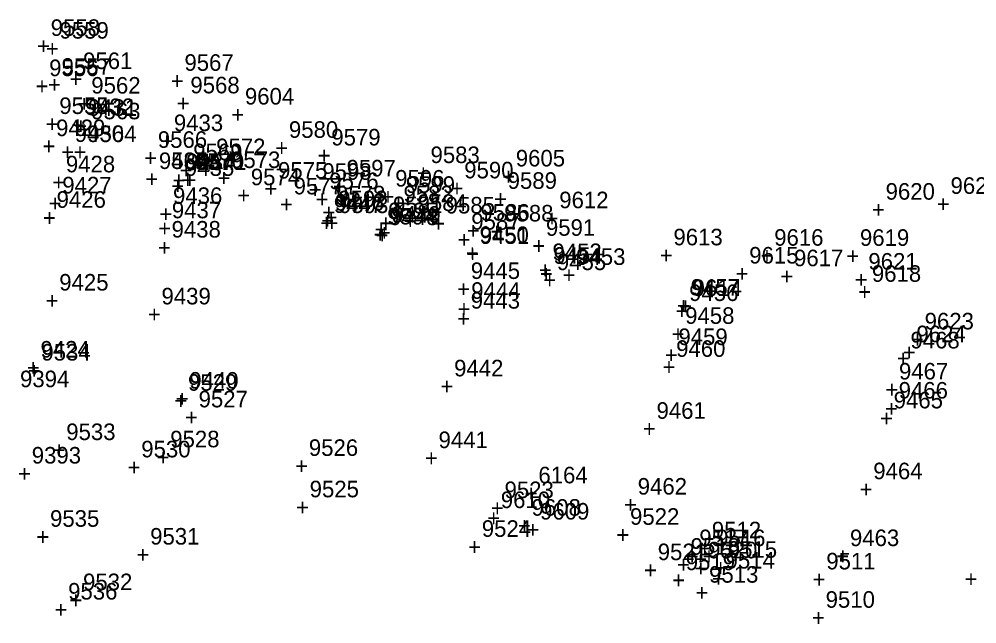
# Model space of a CAD drawing. Extents: x 1136220 to 1137808, y 528804 to 531215.
# Drawn here: x 1136494.7 to 1136639.3, y 529219.5 to 529310.9 of the extents above; entities that cross this region are included whole.
import ezdxf

# ---------------------------------------------------------------- set-up
doc = ezdxf.new("R2010")
doc.units = 0
for name, color, linetype in [('S_Buildings', 7, 'Continuous'), ('S_Buildings_Attachments', 7, 'Continuous'), ('S_Buildings_Steps_Brick', 7, 'Continuous'), ('S_Drainage_CB', 7, 'Continuous'), ('S_Fencing_ChainLink', 7, 'Continuous'), ('S_Fencing_Gate', 7, 'Continuous'), ('S_Fencing_Picket', 7, 'Continuous'), ('S_Ground_Elevation', 7, 'Continuous'), ('S_Ground_LevelString', 7, 'Continuous'), ('S_Property_Light', 7, 'Continuous'), ('S_RetWall_Top', 7, 'Continuous'), ('S_Roadway_Centerline', 7, 'Continuous'), ('S_Roadway_Drive_Gravel', 7, 'Continuous'), ('S_Roadway_Drive_Paved', 7, 'Continuous'), ('S_Roadway_Edge_Pavement', 7, 'Continuous'), ('S_Roadway_Sidewalks', 7, 'Continuous'), ('S_Traffic_Sign_SinglePost', 7, 'Continuous'), ('S_Trees_Bush', 7, 'Continuous'), ('S_Trees_Decid_Pay', 7, 'Continuous'), ('S_Trees_HedgeLine', 7, 'Continuous'), ('S_Utilities_Pole_Power', 7, 'Continuous'), ('S_Utilities_UG_Gas_Line', 7, 'Continuous')]:
    doc.layers.add(name, color=color, linetype=linetype)

msp = doc.modelspace()

# ---------------------------------------------------------------- texts
at = {"layer": 'S_Buildings'}
for s, p in [('9604', (1136528.8, 529297.96)), ('+', (1136526.74, 529295.21)), ('9605', (1136569.68, 529288.61)), ('+', (1136567.62, 529285.86))]:
    msp.add_text(s, height=2.5, dxfattribs=at).set_placement(p)
at = {"layer": 'S_Buildings_Attachments'}
for s, p in [('9598', (1136540.49, 529286.6)), ('+', (1136538.43, 529283.85)), ('9599', (1136553.08, 529284.62)), ('+', (1136551.02, 529281.87))]:
    msp.add_text(s, height=2.5, dxfattribs=at).set_placement(p)
at = {"layer": 'S_Buildings_Steps_Brick'}
for s, p in [('9597', (1136544.14, 529287.1)), ('9596', (1136551.48, 529285.57)), ('+', (1136542.08, 529284.35)), ('9592', (1136542.89, 529282.45)), ('+', (1136549.42, 529282.82)), ('9593', (1136543.01, 529281.57)), ('9595', (1136550.44, 529280.64)), ('+', (1136540.83, 529279.7)), ('9594', (1136550.28, 529279.85)), ('+', (1136540.95, 529278.82)), ('+', (1136548.22, 529277.1)), ('+', (1136548.38, 529277.89))]:
    msp.add_text(s, height=2.5, dxfattribs=at).set_placement(p)
at = {"layer": 'S_Drainage_CB'}
for s, p in [('9520', (1136598.7, 529229.43)), ('+', (1136596.64, 529226.68))]:
    msp.add_text(s, height=2.5, dxfattribs=at).set_placement(p)
at = {"layer": 'S_Fencing_ChainLink'}
for s, p in [('9535', (1136499.39, 529234.2)), ('+', (1136497.33, 529231.45)), ('9536', (1136502.12, 529223.21)), ('+', (1136500.06, 529220.46))]:
    msp.add_text(s, height=2.5, dxfattribs=at).set_placement(p)
at = {"layer": 'S_Fencing_Gate'}
for s, p in [('9433', (1136518.08, 529293.95)), ('+', (1136516.02, 529291.2)), ('9453', (1136578.79, 529273.74)), ('+', (1136576.73, 529270.99))]:
    msp.add_text(s, height=2.5, dxfattribs=at).set_placement(p)
at = {"layer": 'S_Fencing_Picket'}
for s, p in [('9432', (1136504.65, 529296.37)), ('9429', (1136500.3, 529293.19)), ('+', (1136502.59, 529293.62)), ('+', (1136498.24, 529290.44)), ('9434', (1136519.93, 529288.05)), ('+', (1136517.87, 529285.3)), ('9620', (1136625.49, 529283.59)), ('9446', (1136542.37, 529281.93)), ('+', (1136623.43, 529280.84)), ('9449', (1136550.92, 529280.12)), ('+', (1136540.31, 529279.18)), ('+', (1136548.86, 529277.37)), ('9450', (1136564.21, 529277.04)), ('9616', (1136608.68, 529276.64)), ('9619', (1136621.62, 529276.62)), ('+', (1136562.15, 529274.29)), ('9452', (1136575.21, 529274.47)), ('+', (1136606.62, 529273.89)), ('+', (1136619.55, 529273.87)), ('+', (1136573.15, 529271.72)), ('9457', (1136596.08, 529269.1)), ('9614', (1136596.37, 529269.03)), ('+', (1136594.02, 529266.35)), ('+', (1136594.31, 529266.28))]:
    msp.add_text(s, height=2.5, dxfattribs=at).set_placement(p)
at = {"layer": 'S_Ground_Elevation'}
for s, p in [('9558', (1136499.49, 529308.32)), ('+', (1136497.43, 529305.57)), ('9556', (1136499.26, 529302.25)), ('9568', (1136520.57, 529299.65)), ('+', (1136497.2, 529299.5)), ('+', (1136518.51, 529296.9)), ('9431', (1136505.11, 529296.25)), ('+', (1136503.05, 529293.5)), ('9430', (1136503.12, 529292.31)), ('9580', (1136535.44, 529292.93)), ('9579', (1136541.84, 529291.78)), ('+', (1136501.06, 529289.56)), ('9569', (1136521, 529289.55)), ('+', (1136533.37, 529290.18)), ('9583', (1136556.81, 529289.12)), ('9573', (1136526.71, 529288.37)), ('+', (1136539.78, 529289.03)), ('+', (1136518.94, 529286.8)), ('9590', (1136561.9, 529286.81)), ('+', (1136524.65, 529285.62)), ('+', (1136554.75, 529286.37)), ('9589', (1136568.45, 529285.23)), ('+', (1136559.83, 529284.06)), ('9584', (1136554.85, 529281.89)), ('+', (1136566.39, 529282.48)), ('9588', (1136567.93, 529280.3)), ('+', (1136552.79, 529279.14)), ('+', (1136565.86, 529277.55)), ('9613', (1136593.47, 529276.7)), ('+', (1136591.41, 529273.95)), ('9615', (1136604.91, 529273.95)), ('9617', (1136611.67, 529273.54)), ('+', (1136602.85, 529271.2)), ('+', (1136609.61, 529270.79)), ('9618', (1136623.42, 529271.19)), ('+', (1136621.36, 529268.44)), ('9394', (1136494.86, 529255.28)), ('9527', (1136521.81, 529252.23)), ('+', (1136519.75, 529249.48)), ('9528', (1136517.53, 529246.2)), ('9526', (1136538.45, 529244.9)), ('9393', (1136496.63, 529243.75)), ('+', (1136515.47, 529243.45)), ('+', (1136536.38, 529242.15)), ('+', (1136494.56, 529241)), ('9525', (1136538.57, 529238.65)), ('9523', (1136567.98, 529238.53)), ('+', (1136536.51, 529235.9)), ('+', (1136565.92, 529235.78)), ('9522', (1136586.92, 529234.5)), ('9524', (1136564.55, 529232.68)), ('+', (1136584.86, 529231.75)), ('9517', (1136597.38, 529231.27)), ('9512', (1136599.27, 529232.46)), ('9516', (1136599.92, 529231.27)), ('9518', (1136596.06, 529229.98)), ('+', (1136562.49, 529229.93)), ('9521', (1136591.1, 529229.16)), ('+', (1136597.21, 529229.71)), ('9515', (1136601.68, 529229.52)), ('+', (1136595.32, 529228.52)), ('9519', (1136595.33, 529227.65)), ('+', (1136597.86, 529228.52)), ('9514', (1136601.34, 529227.89)), ('9511', (1136616.54, 529227.76)), ('+', (1136589.04, 529226.41)), ('+', (1136594, 529227.23)), ('9513', (1136598.85, 529225.76)), ('+', (1136599.62, 529226.77)), ('+', (1136593.27, 529224.9)), ('+', (1136599.28, 529225.14)), ('+', (1136614.48, 529225.01)), ('+', (1136596.79, 529223.01)), ('9510', (1136616.44, 529221.97)), ('+', (1136614.38, 529219.22))]:
    msp.add_text(s, height=2.5, dxfattribs=at).set_placement(p)
at = {"layer": 'S_Ground_LevelString'}
for s, p in [('9428', (1136501.78, 529287.72)), ('+', (1136499.72, 529284.97)), ('9427', (1136501.24, 529284.54)), ('9436', (1136517.95, 529282.95)), ('+', (1136499.18, 529281.79)), ('9437', (1136517.77, 529280.78)), ('+', (1136515.89, 529280.2)), ('+', (1136515.71, 529278.03)), ('9445', (1136562.89, 529271.62)), ('+', (1136560.83, 529268.87)), ('9444', (1136562.95, 529268.62)), ('+', (1136560.89, 529265.87)), ('9458', (1136595.24, 529264.84)), ('+', (1136593.18, 529262.09)), ('9459', (1136594.22, 529261.64)), ('+', (1136592.16, 529258.89)), ('9467', (1136627.51, 529256.44)), ('+', (1136625.45, 529253.69)), ('9466', (1136627.46, 529253.56)), ('+', (1136625.39, 529250.81))]:
    msp.add_text(s, height=2.5, dxfattribs=at).set_placement(p)
at = {"layer": 'S_Property_Light'}
for s, p in [('9557', (1136501.13, 529302.46)), ('+', (1136499.07, 529299.71))]:
    msp.add_text(s, height=2.5, dxfattribs=at).set_placement(p)
at = {"layer": 'S_RetWall_Top'}
for s, p in [('9570', (1136521.25, 529288.09)), ('9571', (1136521.58, 529288.09)), ('+', (1136519.19, 529285.34)), ('+', (1136519.52, 529285.34)), ('9574', (1136529.69, 529285.77)), ('9577', (1136536.15, 529284.39)), ('+', (1136527.63, 529283.02)), ('9578', (1136542.55, 529283.18)), ('+', (1136534.09, 529281.64)), ('9581', (1136551.15, 529281.56)), ('+', (1136540.49, 529280.43)), ('9587', (1136562.96, 529279.06)), ('+', (1136549.09, 529278.81)), ('9591', (1136574.23, 529278.14)), ('+', (1136560.9, 529276.31)), ('+', (1136572.17, 529275.39))]:
    msp.add_text(s, height=2.5, dxfattribs=at).set_placement(p)
at = {"layer": 'S_Roadway_Centerline'}
for s, p in [('9425', (1136500.78, 529269.87)), ('9439', (1136516.21, 529267.78)), ('+', (1136498.72, 529267.12)), ('+', (1136514.15, 529265.03)), ('9442', (1136560.37, 529256.91)), ('+', (1136558.31, 529254.16)), ('9461', (1136590.92, 529250.51)), ('+', (1136588.86, 529247.76)), ('9464', (1136623.63, 529241.38)), ('+', (1136621.57, 529238.63))]:
    msp.add_text(s, height=2.5, dxfattribs=at).set_placement(p)
at = {"layer": 'S_Roadway_Drive_Gravel'}
for s, p in [('9622', (1136635.29, 529284.47)), ('+', (1136633.22, 529281.72)), ('9623', (1136631.38, 529264)), ('9624', (1136630.14, 529262.07)), ('+', (1136629.32, 529261.25)), ('+', (1136628.08, 529259.32))]:
    msp.add_text(s, height=2.5, dxfattribs=at).set_placement(p)
at = {"layer": 'S_Roadway_Drive_Paved'}
for s, p in [('9559', (1136500.82, 529307.91)), ('+', (1136498.76, 529305.16)), ('9561', (1136504.38, 529303.32)), ('9567', (1136519.67, 529303.05)), ('+', (1136502.32, 529300.57)), ('9562', (1136505.62, 529299.61)), ('+', (1136517.61, 529300.3)), ('+', (1136503.56, 529296.86)), ('9563', (1136505.6, 529295.73)), ('+', (1136503.54, 529292.98)), ('9564', (1136505, 529292.29)), ('9566', (1136515.66, 529291.42)), ('+', (1136502.94, 529289.54)), ('+', (1136513.59, 529288.67)), ('9565', (1136515.82, 529288.22)), ('+', (1136513.76, 529285.47)), ('9534', (1136498.09, 529259.3)), ('+', (1136496.03, 529256.55)), ('9529', (1136520.21, 529254.74)), ('+', (1136518.15, 529251.99)), ('9533', (1136501.84, 529247.29)), ('9530', (1136513.16, 529244.68)), ('+', (1136499.78, 529244.54)), ('+', (1136511.1, 529241.93)), ('9531', (1136514.5, 529231.51)), ('+', (1136512.43, 529228.76)), ('9532', (1136504.37, 529224.63)), ('+', (1136502.31, 529221.88))]:
    msp.add_text(s, height=2.5, dxfattribs=at).set_placement(p)
at = {"layer": 'S_Roadway_Edge_Pavement'}
for s, p in [('9426', (1136500.38, 529282.37)), ('+', (1136498.32, 529279.62)), ('9438', (1136517.73, 529277.87)), ('+', (1136515.67, 529275.12)), ('9443', (1136562.88, 529267.14)), ('+', (1136560.82, 529264.39)), ('9424', (1136497.94, 529259.75)), ('9460', (1136593.88, 529259.86)), ('+', (1136495.88, 529257)), ('+', (1136591.82, 529257.11)), ('9440', (1136520.41, 529255.06)), ('+', (1136518.35, 529252.31)), ('9465', (1136626.71, 529252.08)), ('+', (1136624.65, 529249.33)), ('9441', (1136558.02, 529246.08)), ('+', (1136555.96, 529243.33)), ('9462', (1136588.08, 529239.06)), ('+', (1136586.01, 529236.31)), ('9463', (1136620.11, 529231.28)), ('+', (1136618.05, 529228.53)), ('+', (1136637.4, 529225.09))]:
    msp.add_text(s, height=2.5, dxfattribs=at).set_placement(p)
at = {"layer": 'S_Roadway_Sidewalks'}
for s, p in [('9434A', (1136515.82, 529288.22)), ('9435', (1136519.75, 529287.18)), ('+', (1136513.76, 529285.47)), ('+', (1136517.69, 529284.43)), ('9447', (1136542.21, 529281.6)), ('9448', (1136550.59, 529279.75)), ('+', (1136540.15, 529278.85)), ('+', (1136548.53, 529277)), ('9451', (1136564.26, 529276.91)), ('+', (1136562.19, 529274.16)), ('9454', (1136575.36, 529273.91)), ('9455', (1136575.88, 529272.96)), ('+', (1136573.3, 529271.16)), ('+', (1136573.82, 529270.21)), ('9456', (1136595.84, 529268.29)), ('+', (1136593.78, 529265.54)), ('9468', (1136629.24, 529261.13)), ('+', (1136627.18, 529258.38))]:
    msp.add_text(s, height=2.5, dxfattribs=at).set_placement(p)
at = {"layer": 'S_Traffic_Sign_SinglePost'}
for s, p in [('9610', (1136567.42, 529237.02)), ('+', (1136565.36, 529234.27))]:
    msp.add_text(s, height=2.5, dxfattribs=at).set_placement(p)
at = {"layer": 'S_Trees_Bush'}
for s, p in [('9572', (1136524.46, 529290.31)), ('+', (1136522.4, 529287.56)), ('9575', (1136533.8, 529286.77)), ('9576', (1136541.53, 529285.18)), ('+', (1136531.74, 529284.02)), ('+', (1136539.47, 529282.43)), ('9582', (1136552.73, 529283.21)), ('9612', (1136576.24, 529282.3)), ('9585', (1136559.1, 529281.51)), ('9586', (1136564.34, 529280.43)), ('+', (1136550.67, 529280.46)), ('+', (1136574.17, 529279.55)), ('+', (1136557.04, 529278.76)), ('+', (1136562.28, 529277.68))]:
    msp.add_text(s, height=2.5, dxfattribs=at).set_placement(p)
at = {"layer": 'S_Trees_Decid_Pay'}
for s, p in [('9621', (1136622.89, 529273.03)), ('+', (1136620.83, 529270.28))]:
    msp.add_text(s, height=2.5, dxfattribs=at).set_placement(p)
at = {"layer": 'S_Trees_HedgeLine'}
for s, p in [('9555', (1136500.79, 529296.53)), ('+', (1136498.73, 529293.78))]:
    msp.add_text(s, height=2.5, dxfattribs=at).set_placement(p)
at = {"layer": 'S_Utilities_Pole_Power'}
for s, p in [('9608', (1136572.06, 529235.87)), ('9609', (1136573.34, 529235.29)), ('+', (1136570, 529233.12)), ('+', (1136571.28, 529232.54))]:
    msp.add_text(s, height=2.5, dxfattribs=at).set_placement(p)
at = {"layer": 'S_Utilities_UG_Gas_Line'}
for s, p in [('6164', (1136573.09, 529240.76)), ('+', (1136571.03, 529238.01))]:
    msp.add_text(s, height=2.5, dxfattribs=at).set_placement(p)

doc.saveas('drawing.dxf')
